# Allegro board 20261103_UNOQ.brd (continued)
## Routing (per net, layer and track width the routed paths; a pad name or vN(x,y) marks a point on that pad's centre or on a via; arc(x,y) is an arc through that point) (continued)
FORCED_USB_BOOT_N_R: length 12.3
  G7 w0.064: v1(14.73,23.6) 14.73,26.92 11.45,30.2 7.48,30.2 7.32,30.36 v1(7.31,30.36)
  BOTTOM w0.066: MCU1.A5 v1(14.73,23.6)
FORCED_USB_BOOT_POL_SEL: length 22.1
  TOP w0.066: v3(20.61,30.93) 20.77,30.77 20.77,28.91 21.18,28.5 21.18,27.4 21.45,27.13 21.45,18.4 22.21,17.64 R1314.1 R1313.2
  S3 w0.064: v3(26.57,29.68) 26.38,29.87 26.01,29.87 25.81,29.67 22.26,29.67 21.51,30.42 21.12,30.42 v3(20.61,30.93)
HPH_L: length 22.8
  TOP w0.15: PMIC1.L27 42.63,15.98 v3(42.67,16.02)
  S3 w0.15: v3(42.67,16.02) 42.65,15.99 v4(42.39,15.99)
  S6 w0.15: v4(42.39,15.99) 42.39,16.29 v1(42.4,16.3)
  BOTTOM w0.15: R2634.2 23.27,15.61 23.61,15.95 32.57,15.95 33.26,16.64 35.52,16.64 36.2,15.96 38.51,15.96 39.15,16.6 42.1,16.6 v1(42.4,16.3)
HPH_L_CONN: length 2.4
  BOTTOM w0.15: R2634.1 23.24,14.25 D26089.2 23.24,13.26 23.49,13 23.49,11.98
HPH_R: length 23.4
  TOP w0.15: v3(42.67,17.07) 42.39,17.07 41.87,16.55 PMIC1.J27
  S3 w0.15: v3(42.67,17.07) 42.67,17.07 v4(42.37,17.07)
  S6 w0.15: v4(42.37,17.07) v1(42.05,17.07)
  BOTTOM w0.15: v1(42.05,17.07) 41.86,16.88 39.02,16.88 38.33,16.19 36.39,16.19 35.6,16.98 33.14,16.98 32.47,16.31 23.38,16.31 22.73,15.66 R2635.2
HPH_R_CONN: length 2.5
  BOTTOM w0.15: 22.22,11.98 22.22,12.75 22.73,13.26 D26090.2 22.73,14.27 R2635.1
HPH_REF: length 27.4
  TOP w0.15: 42.12,16.26 PMIC1.K26
  TOP w0.2: 42.12,16.26 42.4,16.54 v3(42.67,16.54)
  S3 w0.2: v3(42.67,16.54) 42.92,16.54 42.93,16.54 v4(42.95,16.54)
  S6 w0.2: v1(42.65,16.54) v4(42.95,16.54)
  BOTTOM w0.2: v1(42.65,16.54) 42.65,17.15 ; R2633.2 22,14.59 22,15.98 22.99,16.97 29.66,16.97 30.71,18.02 35.19,18.02 36.67,16.54 38.19,16.54 39.3,17.65 41.8,17.65
  BOTTOM w0.203: 42.65,17.15 42.15,17.65 41.8,17.65
HPH_REF_CONN: length 2.1
  BOTTOM w0.203: R2633.1 21.68,13.39 20.95,12.66 20.95,11.98
HS_DET: length 51.5
  TOP w0.1: v3(43.81,20.02) 43.9,19.93 46.98,19.93 48.11,18.8 48.11,7.66 47.78,7.33 23.05,7.33 22.42,7.96 v3(22.42,8.72)
  S3 w0.064: v3(22.42,8.72) v4(22.42,9.16)
  S3 w0.1: v3(40.36,18.19) 40.39,18.21 40.39,18.29 41.2,19.1 42.09,19.1 42.75,19.76 43.56,19.76 v3(43.81,20.02)
  S6 w0.1: v4(22.42,9.16) 19.76,11.82 v1(19.68,11.82)
  BOTTOM w0.1: 19.68,11.98 v1(19.68,11.82)
JTAG_PS_HOLD: length 22
  TOP w0.066: v3(22.79,8.38) 35.02,8.38 R709.2
  S3 w0.064: v4(20.4,2.8) 20.12,3.08 20.12,5.5 22.79,8.17 v3(22.79,8.38)
  S6 w0.064: v1(21.71,2.8) v4(20.4,2.8)
  BOTTOM w0.066: v1(21.71,2.8) 22.37,2.14 22.64,2.14 TP1213.1
LDO1_EN: length 2
  BOTTOM w0.066: SB2801.2 11.68,39.33 R2801.2 11.7,40.05 U2801.1
LDO1_FB: length 3
  BOTTOM w0.203: U2801.6 13.6,41.08 12.83,40.31 R2803.1 12.83,40.01 R2802.2 13.34,40.01 C2803.2
LDO1_PG: length 8.2
  BOTTOM w0.203: Q2802.1 17.58,44.86 17.58,41.51 17.44,41.37 R2810.1 17.08,41.26 C2808.1 15.94,41.26 15.11,42.09 15.11,42.32 14.43,42.32 U2801.5
LDO2_EN: length 1
  BOTTOM w0.066: R2804.2 10.5,32.46 10.52,32.48 U2802.1
LDO2_FB: length 2.8
  BOTTOM w0.066: R2805.2 12.22,31.43 C2807.2 12.23,31.45 R2806.1 12.23,32.7 12.69,33.15 U2802.6
LED_MATRIX_0: length 22.5
  S3 w0.1: v3(19.03,7.74) 19.01,7.72 16.42,7.72 15.04,9.1 v4(13.22,9.1)
  S6 w0.1: v5(12.09,21.39) 12.04,21.34 12.04,18.67 9.32,15.95 9.32,13.49 13.18,9.63 13.18,9.14 v4(13.22,9.1)
  G7 w0.1: v5(12.09,21.39) 12.17,21.39 v1(12.9,22.11)
LED_MATRIX_0_R: length 84
  TOP w0.1: v2(10.04,21.05) 9.88,21.05 D27074.2 8.63,20.36 v2(8.36,20.36) ; D27091.1 v2(8,10.77) ; 15.39,26.86 v2(14.91,26.39) ; 15.39,26.86 15.88,27.35 v2(16.04,27.35) ; 15.39,26.86 15.39,27.03 13.42,29 ; 13.42,29 13.88,29.45 D27043.1 ; 13.42,29 D27044.2 12.91,28.22 D27057.1 11.07,26.39 v2(10.91,26.39) ; 19.48,35.36 D27002.2 ; 19.48,35.36 19.88,35.75 v2(20.04,35.75) ; 19.48,35.36 17.95,36.89 D27014.2 16.02,37.77 5.79,37.77 D27092.2 ; R2711.2 19.03,9.54 v2(20.04,10.55) ; D27003.1 19.07,30.59 D27004.2 18.91,30.26 v2(18.53,29.88) ; D27007.1 19.88,23.15 D27008.2 18.91,21.92 D27021.1 17.07,20.09 D27022.2
  G2 w0.1: v2(14.91,26.39) 14.68,26.39 13.58,25.29 13.58,23.02 v2(16.51,20.09) ; v2(10.91,26.39) 10.45,26.39 9.47,25.41 9.47,21.62 v2(10.04,21.05) ; v2(20.42,31.56) 20.42,35.37 v2(20.04,35.75) ; v2(18.53,29.88) 16.04,27.39 v2(16.04,27.35) ; v2(8.36,20.36) 6.31,18.31 6.31,12.4 D27091.1 v2(8,10.77) 8.23,11 11.92,11 12.67,10.25 16.48,10.25 16.78,10.55 v2(20.04,10.55)
LED_MATRIX_1: length 25.9
  S3 w0.1: v4(13.77,8.51) 15.02,8.51 16.17,7.36 21.25,7.36 v3(21.85,7.96)
  S6 w0.1: v4(13.77,8.51) 13.77,9.35 9.55,13.56 9.55,15.72 12.29,18.47 12.29,20.8 12.42,20.93 12.42,22.59 v1(12.4,22.61)
LED_MATRIX_1_R: length 74.8
  TOP w0.1: D27034.2 15.07,22.19 15.51,22.63 ; v2(20.04,33.65) D27015.1 17.88,33.65 v2(16.91,32.69) ; 15.51,22.63 15.51,22.76 13.53,24.74 ; 15.51,22.63 v2(16.04,23.15) ; v2(10.91,22.19) 11.07,22.19 D27059.1 12.04,23.42 D27046.2 13.07,24.29 13.53,24.74 ; v2(18.37,25.85) D27006.2 19.07,26.39 D27005.1 ; 13.53,24.74 D27045.1 14.23,25.06 v2(14.8,25.06) ; v2(20.59,17.83) 20.59,18.4 D27009.1 19.07,17.99 D27010.2 18.04,17.12 D27023.1 17.07,15.89 v2(16.91,15.89) ; D27076.2 9.07,15.89 v2(10.04,16.85) ; D27094.2 5.88,33.65 D27093.1 6.04,33.65 v2(6.33,33.65)
  G2 w0.1: v2(16.04,23.15) 16.04,20.91 16.8,20.15 16.8,18.86 16.44,18.5 16.44,16.35 v2(16.91,15.89) ; v2(20.59,17.83) 21.16,17.83 21.85,17.14 v2(21.85,8.92) ; v2(6.33,33.65) 7.09,33.65 8.79,35.35 10.44,35.35 12.75,33.04 15.39,33.04 15.74,32.69 v2(16.91,32.69) ; v2(20.4,27.37) 20.04,27.73 v2(20.04,33.65) 20.04,34.51 18.91,35.64 v2(18.91,36.89) ; v2(10.04,16.85) 10.39,17.2 10.39,20.55 10.91,21.07 v2(10.91,22.19) ; v2(14.8,25.06) 15.08,25.34 17.19,25.34 17.7,25.85 v2(18.37,25.85)
LED_MATRIX_2: length 26.1
  S3 w0.1: v4(12.52,9.02) 12.73,9.02 12.94,8.81 15.03,8.81 16.3,7.54 20.44,7.54 v3(20.89,7.99)
  S6 w0.1: v4(12.52,9.02) 12.52,9.96 9.07,13.41 9.07,16.08 11.79,18.8 11.79,20.31 11.81,20.33 11.81,21.51 12.19,21.89 12.19,22.76 12.4,22.97 v1(12.4,23.11)
LED_MATRIX_2_R: length 84
  TOP w0.1: 15.47,18.55 15.88,18.95 D27035.1 ; 15.47,18.55 D27036.2 ; 15.47,18.55 15.44,18.55 13.41,20.58 ; 13.41,20.58 D27048.2 12.91,19.82 D27061.1 11.88,18.95 v2(10.91,17.99) ; 13.41,20.58 13.88,21.05 D27047.1 ; D27011.1 19.07,13.79 D27012.2 18.04,12.92 D27025.1 17.07,11.69 v2(16.91,11.69) ; D27011.1 21.14,15.85 21.14,24.15 D27006.1 20.83,26.04 20.83,28.17 20.04,28.96 D27004.1 19.88,29.45 D27005.2 18.04,29.35 D27017.1 ; D27011.1 21.15,13.64 21.15,9.21 R2702.2 ; D27018.2 17.07,28.49 D27017.1 ; v2(10.04,12.23) D27077.1 ; v2(6.45,29.04) D27095.1 5.07,28.49 D27096.2 ; D27017.1 18.04,30.61 18.91,31.48 D27003.2
  G2 w0.1: v2(10.04,12.23) 10.04,11.55 10.31,11.28 ; v2(6.45,29.04) 7.34,28.15 7.34,22.71 8.91,21.14 8.91,20.39 7.6,19.07 7.6,14.67 9.21,13.06 10.33,13.06 10.91,12.48 ; v2(8.91,11.69) 9.31,11.28 10.31,11.28 ; 10.31,11.28 12.11,11.28 ; 12.11,11.28 12.78,10.61 15.31,10.61 16.39,11.69 v2(16.91,11.69) ; 12.11,11.28 10.91,12.48 ; 10.91,12.48 v2(10.91,17.99)
LED_MATRIX_3: length 28.1
  S3 w0.1: v3(19.95,7.99) 18.46,7.99 18.09,8.36 16.69,8.36 15.19,9.86 12.89,9.86 11.45,11.3 8.46,11.3 v4(8.32,11.16)
  S6 w0.1: v5(11.35,23.47) 11.35,23.4 11.21,23.26 11.21,22.94 9.86,21.59 9.86,19.05 7.85,17.04 7.85,12.7 8.05,12.5 8.05,11.43 v4(8.32,11.16)
  G7 w0.1: v1(12.06,23.45) 12.04,23.45 12.04,23.47 11.9,23.61 11.49,23.61 v5(11.35,23.47)
  BOTTOM w0.1: v1(12.06,23.45) 12.04,23.45 12.04,23.47 MCU1.G5
LED_MATRIX_3_R: length 75.7
  TOP w0.1: 13.42,16.39 14.91,14.9 D27038.2 15.88,14.75 v2(16.04,14.75) ; 13.42,16.39 13.88,16.85 D27049.1 ; 13.42,16.39 D27050.2 12.04,15.02 D27063.1 11.07,13.79 D27064.2 ; D27008.1 20.8,21.81 20.8,23.62 20.13,24.29 D27007.2 18.04,25.15 D27019.1 ; D27008.1 20.84,20.25 20.84,17.65 D27010.1 19.07,15.89 v2(18.91,15.89) ; D27008.1 19.88,21.05 D27009.2 ; v2(6.04,25.25) 5.07,24.29 D27098.2 ; v2(20.04,12.65) 20.82,11.87 20.82,9.9 19.95,9.03 R2703.2 ; v2(8.04,35.75) 7.88,35.75 D27080.2 ; D27019.1 17.88,25.25 D27020.2 ; D27019.1 v2(18.84,25.25) ; v2(14.91,34.79) 15.88,35.75 D27027.1
  G2 w0.1: v2(18.91,15.89) 20.04,14.75 v2(20.04,12.65) 19.03,12.65 16.93,14.75 v2(16.04,14.75) ; v2(6.04,25.25) 6.04,29.25 6.92,30.13 6.92,31.31 5.86,32.37 5.86,34.12 7.49,35.75 v2(8.04,35.75) 10.93,35.75 11.89,34.79 v2(14.91,34.79) 15.26,34.43 16.98,34.43 17.71,33.7 17.71,31.29 19.17,29.83 19.17,25.58 v2(18.84,25.25)
LED_MATRIX_4: length 24.1
  S3 w0.1: v4(10.08,10.99) 10.13,11.04 11.43,11.04 12.83,9.64 15.1,9.64 16.61,8.13 v3(17.21,8.13)
  S6 w0.1: v1(11.9,24.11) 11.9,23.4 11.56,23.07 11.56,22.8 10.29,21.53 10.29,18.82 8.23,16.76 8.23,12.98 8.84,12.37 8.84,11.66 9.32,11.18 9.89,11.18 v4(10.08,10.99)
LED_MATRIX_4_R: length 81.2
  TOP w0.1: v2(6.04,21.05) 5.07,20.09 D27100.2 ; D27030.2 15.88,31.55 D27029.1 16.04,31.45 D27017.2 ; D27015.2 17.88,35.75 v2(18.04,35.75) ; D27081.1 7.88,31.55 D27082.2 ; D27065.1 12.04,10.82 D27052.2 13.07,11.69 13.54,12.15 ; 13.54,12.15 D27051.1 ; 13.54,12.15 15.14,10.55 v2(16.04,10.55) 17.21,9.38 R2704.2 ; D27017.2 17.88,31.55 v2(18.04,31.55) ; D27017.2 16.91,29.38 16.03,28.5 16.03,28.36 17.04,27.35 17.88,27.35 ; 17.88,27.35 D27019.2 16.8,26.28 16.8,25.41 v2(17.15,25.06) ; 17.88,27.35 D27018.1
  G2 w0.1: v2(6.04,21.05) 5.76,21.33 5.76,29.77 v2(6.57,30.58) 6.57,30.92 5.51,31.98 5.51,35.14 7.65,37.28 v2(8.9,37.28) 8.92,37.26 v2(12.92,37.26) 15.58,37.26 17.09,35.75 v2(18.04,35.75) 18.51,35.28 18.51,32.02 v2(18.04,31.55) ; v2(16.04,10.55) 16.77,11.28 18.5,11.28 v2(18.91,11.69) 19.76,11.69 20.56,12.49 20.56,15.04 19.32,16.28 18.65,16.28 18.39,16.02 17.19,16.02 16.62,16.59 16.62,18.29 17.03,18.7 17.03,20.32 16.66,20.69 16.66,21.5 18.04,22.88 v2(18.04,23.15) 18.04,24.17 v2(17.15,25.06)
LED_MATRIX_5: length 28.1
  S3 w0.1: v3(18.08,7.99) 17.99,7.9 16.51,7.9 15,9.41 12.76,9.41 11.86,10.31 10.4,10.31 10.01,9.92 v4(10.01,9.73)
  S6 w0.1: v5(10.95,23.5) 10.87,23.42 10.82,23.42 10.67,23.27 10.67,23.22 10.67,23.22 10.67,22.96 9.47,21.77 9.47,19.23 7.47,17.22 7.47,12.88 7.24,12.65 7.24,11.22 7.66,10.8 9.45,10.8 10.01,10.24 v4(10.01,9.73)
  G7 w0.1: v5(10.95,23.5) 11.18,23.27 11.74,23.27 v1(11.9,23.11)
LED_MATRIX_5_R: length 65.9
  TOP w0.1: R2705.2 18.08,10.51 D27026.1 17.99,10.6 v2(17.99,11.7) ; D27042.2 13.07,32.69 D27041.1 14.04,33.55 v2(14.91,32.69) 15.07,32.69 D27028.1 16.04,34.69 v2(15.78,34.95) ; v2(16.91,13.79) 17.07,13.79 17.5,14.21 ; v2(8.04,27.35) 7.88,27.35 v2(6.91,26.39) ; v2(6.04,16.85) 5.88,16.85 D27102.2 ; v2(17.02,22.91) 16.91,22.81 D27021.2 16.91,20.99 16.11,20.19 16.11,19.89 17.5,18.5 17.5,18.42 ; 17.5,18.42 D27022.1 ; 17.5,18.42 17.07,17.99 D27023.2 16.91,16.81 16.15,16.05 16.15,15.56 17.5,14.21 ; 17.5,14.21 D27024.1 ; v2(8.91,32.69) 9.88,33.65 D27067.1 10.91,34.52 D27054.2 11.88,35.75 v2(12.04,35.75)
  G2 w0.1: v2(12.04,35.75) 12.92,35.75 14.06,36.89 v2(14.91,36.89) 14.91,35.82 v2(15.78,34.95) ; v2(17.99,11.7) 17.93,11.7 16.91,12.72 v2(16.91,13.79) ; v2(14.91,32.69) 14.91,31.65 16.04,30.52 v2(16.04,29.45) 15.48,28.89 15.48,26.37 14.29,25.18 14.29,24.51 15.01,23.79 16.14,23.79 v2(17.02,22.91) ; v2(8.04,27.35) 8.3,27.61 8.3,30.89 8.91,31.5 v2(8.91,32.69) ; v2(6.04,16.85) 6.04,18.58 6.54,19.08 6.54,26.02 v2(6.91,26.39)
LED_MATRIX_6: length 22
  S3 w0.1: v3(7.87,7.76) 8.14,7.49 9.81,7.49 10.59,8.27 v4(10.59,9.92)
  S6 w0.1: v4(10.59,9.92) 10.59,10.01 9.63,10.97 8.99,10.97 8.51,11.46 8.51,12.4 8.03,12.88 8.03,16.89 10.06,18.92 10.06,21.55 11.38,22.87 11.38,23.14 11.63,23.39 11.63,23.88 v1(11.4,24.11)
LED_MATRIX_6_R: length 67.8
  TOP w0.1: 15.54,24.75 D27032.1 ; 15.54,24.75 15.54,24.83 v2(14.04,26.33) ; 15.54,24.75 15.07,24.29 D27033.2 ; 15.54,24.75 16.8,23.49 16.8,23.02 16.04,22.26 D27034.1 15.88,21.05 v2(14.91,20.09) ; v2(14.91,28.49) 14.91,29.56 14.04,30.43 D27042.1 D27055.1 ; v2(17.12,10.09) 17.12,10.49 15.92,11.69 D27039.2 15.88,12.65 v2(16.04,12.65) ; v2(6.04,12.65) 5.88,12.65 D27104.2 4.91,10.55 5.89,9.57 7.02,9.57 R2706.2 ; D27055.1 12.04,32.75 12.84,33.55 12.84,34.72 D27041.2 13.88,35.75 D27040.1 ; D27055.1 11.07,30.59 D27056.2 10.04,29.72 D27069.1 9.07,28.49 v2(8.91,28.49) ; v2(14.91,15.89) 15.07,15.89 D27036.1 ; v2(8.04,23.15) 7.88,23.15 D27086.2
  G2 w0.1: v2(8.91,28.49) 8.91,26.84 8.04,25.97 v2(8.04,23.15) ; v2(6.04,12.65) 6.04,12.15 7.77,10.42 8.04,10.42 8.38,10.76 11.55,10.76 12.22,10.09 v2(17.12,10.09) ; v2(16.04,12.65) 14.91,13.79 v2(14.91,15.89) v2(14.91,20.09) ; v2(14.91,28.49) 14.91,27.2 v2(14.04,26.33)
LED_MATRIX_7: length 18.1
  S3 w0.1: v3(11.34,7.76) 11.97,8.39 11.97,9.86 11.79,10.04 11.27,10.04 v4(11.18,9.95)
  S6 w0.1: v5(11.56,22.11) 11.44,22.11 10.74,21.41 10.74,18.57 8.66,16.48 8.66,13.23 11.18,10.71 v4(11.18,9.95)
  G7 w0.1: v1(11.9,22.11) v5(11.56,22.11)
LED_MATRIX_7_R: length 53.4
  TOP w0.1: D27050.1 13.07,13.79 v2(12.91,13.79) ; v2(12.91,17.99) 13.07,17.99 D27048.1 ; v2(8.91,24.29) 9.88,25.25 v2(10.04,25.25) ; D27043.2 12.04,29.72 v2(12.04,29.45) ; R2707.2 13.17,10.55 D27052.1 ; v2(10.91,32.69) 11.07,32.69 D27054.1 ; v2(10.02,34.88) 10.91,35.77 D27053.2 ; D27046.1 13.88,23.15 v2(12.91,22.19) ; v2(14.04,27.35) 13.88,27.35 D27045.2 ; D27088.2 7.88,18.95 v2(8.04,18.95)
  G2 w0.1: v2(8.04,18.95) 9.26,20.17 9.26,21.39 8.91,21.74 v2(8.91,24.29) ; v2(14.04,27.35) 13.13,27.35 12.93,27.55 ; 10.9,25.25 12.91,23.25 v2(12.91,22.19) v2(12.91,17.99) v2(12.91,13.79) 12.91,12.47 14.04,11.34 v2(14.04,10.94) ; 10.9,25.25 12.93,27.28 12.93,27.55 ; 10.9,25.25 v2(10.04,25.25) ; 12.93,27.55 12.04,28.44 v2(12.04,29.45) 12.04,30.6 10.91,31.73 v2(10.91,32.69) 10.02,33.58 v2(10.02,34.88)
LED_MATRIX_8: length 17.3
  S3 w0.1: v4(11.55,9.6) 11.55,8.85 v3(10.48,7.78)
  S6 w0.1: v5(11.51,21.13) 11.38,21.13 11.05,20.8 11.05,18.44 8.86,16.26 8.86,13.34 11.55,10.65 v4(11.55,9.6)
  G7 w0.1: v1(12.27,21.13) v5(11.51,21.13)
  BOTTOM w0.1: MCU1.F1 v1(12.27,21.13)
LED_MATRIX_8_R: length 47.1
  TOP w0.1: 11.49,24.7 11.49,24.83 9.43,26.89 9.43,26.91 ; 11.49,24.7 11.07,24.29 D27059.2 10.04,23.42 D27072.1 10.04,22.01 11.52,20.53 ; 11.49,24.7 D27058.1 ; 11.51,12.13 D27064.1 ; 11.51,12.13 10.1,13.54 10.1,13.87 10.91,14.68 D27063.2 11.88,16.85 v2(12.04,16.85) ; 11.51,12.13 11.07,11.69 v2(10.91,11.69) 10.91,9.17 R2708.2 ; D27057.2 10.91,28.22 D27070.1 9.88,27.35 9.43,26.91 ; D27089.1 7.88,14.75 v2(6.91,13.79) ; 9.43,31.11 D27069.2 8.91,29.33 8.14,28.56 8.14,28.2 9.43,26.91 ; 9.43,31.11 8.03,32.51 8.03,32.68 8.91,33.56 D27067.2 9.07,34.79 D27066.1 ; 9.43,31.11 9.88,31.55 D27068.1 ; v2(10.91,20.09) 11.07,20.09 11.52,20.53 ; 9.43,26.91 D27071.2 ; 11.52,20.53 D27060.1
  G2 w0.1: v2(10.91,11.69) 10.05,12.55 8.15,12.55 v2(6.91,13.79) ; v2(10.91,20.09) 10.91,19.06 12.04,17.93 v2(12.04,16.85)
LED_MATRIX_9: length 17.9
  S3 w0.1: v4(10.5,10.65) 10.15,10.65 9.65,10.15 9.65,7.88 v3(9.55,7.78)
  S6 w0.1: v1(11.76,22.53) 11.61,22.53 10.52,21.44 10.52,18.73 8.43,16.65 8.43,13.13 9.63,11.94 9.7,11.94 10.5,11.14 v4(10.5,10.65)
  BOTTOM w0.1: v1(11.76,22.53) 11.82,22.53 MCU1.G3
LED_MATRIX_9_R: length 44
  TOP w0.1: 7.46,24.84 7.42,24.84 6.08,26.18 6.08,26.46 6.91,27.29 D27083.2 7.07,28.49 7.54,28.95 ; 7.46,24.84 D27085.2 ; 7.46,24.84 7.88,25.25 D27084.1 8.04,24.02 8.91,23.15 D27073.2 8.04,21.32 D27086.1 7.88,21.05 7.42,20.59 ; D27079.2 6.91,35.67 6.16,34.92 6.16,34.48 7.51,33.13 ; v2(6.91,15.89) 7.07,15.89 D27088.1 8.91,17.72 D27075.2 9.46,18.53 ; 9.46,18.53 9.46,18.55 7.42,20.59 ; 9.46,18.53 9.88,18.95 D27074.1 ; 7.42,20.59 D27087.2 ; 7.51,33.13 D27080.1 ; 7.51,33.13 7.07,32.69 D27081.2 6.91,31.56 6.08,30.73 6.08,30.36 7.49,28.95 7.54,28.95 ; 7.54,28.95 D27082.1 ; D27090.1 8.51,13.12 ; 8.51,13.12 v2(8.51,13.23) 8.91,13.64 D27077.2 9.88,14.75 D27076.1 ; 8.51,13.12 8.51,13.04 10.04,11.51 D27078.1 10.04,9.23 R2709.2
  G2 w0.1: v2(8.51,13.23) 6.91,14.83 v2(6.91,15.89)
LED_MATRIX_10: length 18.1
  S3 w0.1: v3(8.69,7.77) 8.69,9.05 7.79,9.95 v4(7.79,11.14)
  S6 w0.1: v4(7.79,11.14) 7.65,11.28 7.65,17.12 9.65,19.13 9.65,21.67 10.92,22.94 v5(10.92,23.16)
  G7 w0.1: v5(10.92,23.16) 10.97,23.11 11.34,23.11 v1(11.5,22.95)
  BOTTOM w0.1: MCU1.H4 11.4,23.05 v1(11.5,22.95)
LED_MATRIX_10_R: length 38.1
  TOP w0.1: D27100.1 5.07,17.99 v2(4.91,17.99) ; 5.54,14.25 D27102.1 ; 5.54,14.25 5.07,13.79 v2(4.91,13.79) ; 5.54,14.25 5.54,14.16 6.8,12.9 D27091.2 6.04,11.14 D27104.1 6.87,10.55 R2710.2 ; v2(4.91,26.39) 5.07,26.39 D27096.1 ; v2(4.91,34.79) 5.07,34.79 D27092.1 ; v2(4.91,22.19) 5.07,22.19 D27098.1 ; D27094.1 5.88,31.55 v2(4.91,30.59)
  G2 w0.1: v2(4.91,13.79) v2(4.91,17.99) v2(4.91,22.19) v2(4.91,26.39) v2(4.91,30.59) v2(4.91,34.79)
LED_MATRIX_11: length 2.4
  BOTTOM w0.051: MCU1.M5 9.16,23.85 8.61,23.85
  BOTTOM w0.1: 8.61,23.85 7.84,23.08 TP2506.1
LED_PWR: length 2.2
  TOP w0.254: R2735.2 29.81,65.61 D27201.1
LINEOUT_M: length 2.3
  BOTTOM w0.254: C514.1 26.76,15.31 25.19,15.31 25.02,15.14 R2632.2
LINEOUT_M_C: length 26.9
  S3 w0.15: v4(45.23,19.02) 45,19.25 42.95,19.25 41.89,18.2 41.25,18.2 41,17.95 40.68,17.95 v3(40.67,17.96)
  S6 w0.15: v1(45.53,19.04) 45.49,19.08 45.29,19.08 v4(45.23,19.02)
  BOTTOM w0.254: C514.2 27.51,15.21 33.64,15.21 33.91,14.94 38.19,14.94 39.1,15.85 43.85,15.85 44.6,16.6 45.08,16.6 45.9,17.42 45.9,18.67 v1(45.53,19.04)
LINEOUT_M_CONN: length 2.5
  BOTTOM w0.254: 24.76,11.98 24.76,13.01 25.02,13.26 D26088.2 25.02,14.37 R2632.1
LINEOUT_P: length 1.2
  BOTTOM w0.254: R2631.2 26.46,14.88 26.73,14.61 C513.1
LINEOUT_P_C: length 28
  S3 w0.15: v4(45.56,19.45) 45.5,19.51 42.77,19.51 41.74,18.48 41.17,18.48 40.95,18.26 v3(40.95,18.24)
  S6 w0.15: v1(45.85,19.47) 45.81,19.51 45.62,19.51 v4(45.56,19.45)
  BOTTOM w0.254: C513.2 27.71,14.61 27.98,14.88 33.48,14.88 33.77,14.6 38.33,14.6 39.23,15.5 43.98,15.5 44.74,16.26 45.21,16.26 46.24,17.29 46.24,18.83 45.85,19.22 v1(45.85,19.47)
LINEOUT_P_CONN: length 2.5
  BOTTOM w0.254: R2631.1 25.84,14.37 D26087.2 25.84,13.31 26.03,13.12 26.03,11.98
LNBBCLK1: length 6.8
  S3 w0.064: v3(30.3,13.56) 30.49,13.56 30.6,13.45 30.72,13.45 31.5,12.67 32.72,12.67 32.72,12.66 33.53,12.66 33.86,12.99 33.86,13.94 34.77,14.86 35.26,14.86 v3(35.28,14.88)
LNBBCLK2: length 6.1
  S3 w0.064: v3(30.28,12.52) 30.76,12.52 31.08,12.2 33.82,12.2 34.35,12.73 34.48,12.86 34.48,13.7 34.65,13.87 v3(34.65,14.28)
LNBBCLK2_R: length 0.5
  TOP w0.066: R703.1 C720.1
MCU_BOOT0: length 39.8
  S3 w0.064: v4(13.55,35.58) 13.8,35.82 14.55,35.82 14.86,35.51 v4(18.96,35.51)
  S6 w0.064: v1(19.07,36.29) 18.79,36.01 18.79,35.68 v4(18.96,35.51) ; v5(12.89,25.13) 12.89,25.87 11.96,26.8 11.96,32.8 13.55,34.39 v4(13.55,35.58) 13.55,35.87 v1(13.54,35.88) ; v1(6.49,41.7) 6.58,41.79 6.58,42.35 v1(6.31,42.62)
  G7 w0.064: v5(12.89,25.13) 13.67,24.36 13.67,23.85 v1(13.9,23.61)
  BOTTOM w0.066: JANALOG1.1 3.6,41.7 v1(6.49,41.7) 7.72,41.7 10.21,39.2 10.7,39.2 11.53,38.37 12.87,38.37 13.54,37.7 v1(13.54,35.88) ; U1101.10 18.21,37.72 19.24,36.69 19.24,36.43 19.1,36.29 v1(19.07,36.29) ; R2621.1 6.31,43.26 v1(6.31,42.62)
MCU_BOOT0_1P8V: length 12.7
  TOP w0.066: v3(23.72,40.23) 23.83,40.34 24.31,40.34 SOC1.AH1
  S3 w0.064: v3(23.72,40.23) 23.47,39.98 21.11,39.98 20.43,40.66 v4(20.23,40.66)
  S6 w0.064: v1(20,40.44) v4(20.23,40.66)
  BOTTOM w0.066: v1(20,40.44) 19.96,40.39 18.82,40.39 18.65,40.22 15.93,40.22 15.22,39.5 15.22,38.23 15.74,37.71 16.04,37.71 U1101.2
MCU_BT_UART_CTS_R: length 1.8
  TOP w0.064: R2906.2 4.74,61 U2901.14
MCU_BT_UART_RTS_R: length 5.2
  TOP w0.064: R2904.2 4.8,63.17 8.79,63.17 U2901.11
MCU_BT_UART_RX_R: length 7
  TOP w0.064: R2901.2 23.16,62.23 20.82,62.23 20.28,61.69 17.97,61.69 U2901.4
MCU_BT_UART_TX_R: length 2
  TOP w0.064: U2901.41 21.43,60.05 R2908.2
MCU_CRS_SYNC_PA10: length 59.2
  S6 w0.064: v5(4.67,26.49) 4.67,25.32 3.76,24.41 3.76,15.32 4.58,14.5 4.58,6.71 6.04,5.25 9.01,5.25 11.11,3.15 v1(15.1,3.15)
  G7 w0.064: v1(12.4,26.61) 12.16,26.85 8.05,26.85 7.87,27.03 7.39,27.03 6.91,27.51 5.69,27.51 v5(4.67,26.49)
  BOTTOM w0.066: v1(15.1,3.15) 15.84,3.89 23.23,3.89 23.38,4.04 23.38,5.04 24.73,6.39 29.6,6.39 29.84,6.63 JMISC1.25
MCU_I2C2_SCL: length 75.7
  S6 w0.064: v1(8.34,53.48) 8.14,53.28 8.14,46.7 9.07,45.77 9.07,29.91 10.64,28.34 v1(10.64,27.89)
  BOTTOM w0.051: 10.64,25.86 v1(10.64,27.89)
  BOTTOM w0.066: MCU1.K9 10.64,25.86 ; v1(8.34,53.48) 8.59,53.23 11.04,53.23 12.65,51.62 14.51,51.62 18.96,47.17 18.96,43.38 20.38,41.96 33.98,41.96 34.82,42.8 39.75,42.8 43.36,46.41 R2643.2 R2644.1
MCU_I2C2_SCL_CONN: length 10
  BOTTOM w0.066: R2644.2 47.32,46.41 47.68,46.05 51.71,46.05 52.2,46.53 52.2,48.82 51.24,49.78 JDIGITAL1.18
MCU_I2C2_SDA: length 76.4
  S6 w0.064: v1(10.26,27.94) 10.26,28.42 8.87,29.81 8.87,45.75 7.98,46.64 7.98,53.51 v1(7.9,53.59)
  BOTTOM w0.051: 10.13,26.01 10.13,27.81
  BOTTOM w0.066: v1(7.9,53.59) 8,53.69 8.5,53.69 8.8,53.39 11.11,53.39 12.72,51.78 14.58,51.78 19.12,47.23 19.12,43.45 20.45,42.12 33.91,42.12 34.75,42.96 39.63,42.96 43.63,46.96 R2642.2 R2645.1 ; 10.13,27.81 v1(10.26,27.94) ; 10.13,26.01 9.9,25.77 MCU1.L9
MCU_I2C2_SDA_CONN: length 4.3
  BOTTOM w0.066: R2645.2 50.52,46.96 JDIGITAL1.17
MCU_I2C4_SCL_PD12: length 43.9
  TOP w0.066: v3(7.62,7.02) 7.83,7.23 12.95,7.23 13.16,7.44 15.67,7.44 16.01,7.1 R2614.2 16,7.07 R2615.1
  S3 w0.064: v3(7.62,7.02) 5.68,7.02 4.57,5.91 3.86,5.91 3.35,6.42 1.48,6.42 1.07,6.83 1.07,18.28 3.15,20.36 v4(3.15,21.44)
  S6 w0.064: v4(3.15,21.44) 3.39,21.44 v5(3.48,21.35)
  G7 w0.064: v5(3.48,21.35) 3.64,21.35 4.67,22.38 4.67,23.09 4.93,23.34 7.75,23.34 8,23.6 9.58,23.6 9.84,23.86 v1(10.15,23.86)
  BOTTOM w0.051: 10.15,25.74 10.15,25.43 10.21,25.37 10.57,25.37 10.67,25.27 10.67,23.95 10.58,23.86 v1(10.15,23.86)
  BOTTOM w0.066: 10.15,25.74 10.4,25.99 MCU1.K10
MCU_I2C4_SCL_PD12_CONN: length 1.6
  TOP w0.066: R2615.2 15.47,6.41 15.85,6.03 QWIIC1.4
MCU_I2C4_SCL_PF14: length 52.5
  S3 w0.064: v6(3.3,14.2) 5.01,14.2 7.36,11.85 12.32,11.85 13.43,10.74 23.1,10.74 24.62,9.22 v4(25.35,9.22)
  S6 w0.064: v4(25.35,9.22) 25.37,9.19 v5(25.37,8.89)
  G7 w0.064: v5(25.37,8.89) 25.53,9.04 26.61,9.04 31.37,13.81 35.55,13.81 v1(35.82,13.54)
  BOTTOM w0.058: 8.58,24.36 9.65,24.36 MCU1.L6 ; v6(3.3,14.2) 3.63,14.2 4.49,15.05 4.49,21.89 ; 6.54,23.02 7.16,23.64 7.86,23.64
  BOTTOM w0.066: 8.58,24.36 7.86,23.64 ; v1(35.82,13.54) R2668.1 ; 4.49,21.89 5.62,23.02 6.54,23.02
MCU_I2C4_SCL_PF14_CONN: length 1.8
  BOTTOM w0.066: 36.19,11.98 36.19,12.72 36.85,13.38 R2668.2
MCU_I2C4_SDA_PD13: length 48.5
  TOP w0.066: R2616.1 14.34,7.09 ; 14.34,7.09 14.21,7.22 13.21,7.22 13.05,7.06 10.56,7.06 v3(9.2,5.7) ; 14.34,7.09 R2613.2
  S3 w0.064: v4(2.97,26.67) 1.73,26.67 0.56,25.5 0.56,4.72 1.67,3.61 4.48,3.61 5.79,4.92 8.42,4.92 v3(9.2,5.7)
  S6 w0.064: v4(2.97,26.67) 3.07,26.67 v5(3.45,26.29)
  G7 w0.064: v5(3.45,26.29) 3.91,26.29 5.31,27.69 8.79,27.69 9.45,27.03 10.31,27.03 v1(10.4,27.11)
MCU_I2C4_SDA_PD13_CONN: length 1.5
  TOP w0.066: R2616.2 14.86,5.11 QWIIC1.3
MCU_I2C4_SDA_PF15: length 48.9
  S3 w0.064: v6(3.43,13.67) 5.29,13.67 7.29,11.67 12.25,11.67 13.35,10.57 23.08,10.57 24.86,8.79 v4(24.94,8.79)
  S6 w0.064: v5(25.37,8.53) 25.2,8.53 v4(24.94,8.79)
  G7 w0.064: v5(25.37,8.53) 26.41,8.53 31.42,13.54 v1(33.78,13.54)
  BOTTOM w0.058: 6.59,22.86 7.22,23.49 7.92,23.49 ; 4.63,21.83 4.63,14.87 v6(3.43,13.67)
  BOTTOM w0.066: MCU1.N6 8.54,24.11 7.92,23.49 ; 6.59,22.86 5.67,22.86 4.63,21.83 ; R2669.1 v1(33.78,13.54)
MCU_I2C4_SDA_PF15_CONN: length 1.6
  BOTTOM w0.066: R2669.2 34.8,12.1 34.92,11.98
MCU_JTAG_NJTRST_PB4: length 77.2
  TOP w0.066: JDIGITAL1.9 49.5,25.62 49.5,6.91 48.74,6.15 24.66,6.15 23.31,4.8 20.79,4.8 v3(20.7,4.71)
  S3 w0.064: v3(20.7,4.71) 21.71,5.72 21.71,6.75 23.19,8.23 v4(23.19,9.64)
  S6 w0.064: v4(23.19,9.64) 23.19,10.59 20.04,13.74 v1(20.04,16.36)
  BOTTOM w0.066: MCU1.B6 14.64,24.36 16.41,24.36 16.49,24.28 17.55,24.28 TP2504.1 18.9,24.13 20.04,22.99 v1(20.04,16.36)
MCU_JTAG_SWCLK: length 24.2
  S3 w0.064: v4(14.25,35.35) 14.69,35.35 14.99,35.05 19.13,35.05 v4(19.25,35.18)
  S6 w0.064: v4(14.25,35.35) 14.2,35.3 14.2,34.23 13.67,33.7 13.67,30.09 14.48,29.28 14.48,28.35 13.87,27.74 13.87,27.15 13.74,27.03 13.74,26.27 v1(13.9,26.11) ; v4(19.25,35.18) 19.41,35.33 19.41,36.69 19.16,36.94 v1(19.16,37.55)
  BOTTOM w0.051: 15.37,25.86 14.15,25.86 v1(13.9,26.11)
  BOTTOM w0.066: U1101.8 17.46,38.51 18.72,38.51 19.02,38.21 19.02,37.69 v1(19.16,37.55) ; 15.37,25.86 15.75,26.24 17.07,26.24 TP2503.1
MCU_JTAG_SWCLK_1P8V: length 13.3
  S3 w0.064: v3(26.57,39.28) 26.37,39.48 26.37,39.75 25.98,40.13 24.18,40.13 23.75,39.7 20.29,39.7 v4(20.14,39.85)
  S6 w0.064: v4(20.14,39.85) 20.04,39.95 v1(19.75,39.95)
  BOTTOM w0.066: U1101.4 16.04,38.51 15.76,38.51 15.54,38.73 15.54,39.3 16.09,39.85 18.95,39.85 19.05,39.95 v1(19.75,39.95)
MCU_JTAG_SWDIO: length 18.8
  S3 w0.064: v4(14.38,36.42) 14.59,36.63 17.11,36.63 17.75,35.99 19.05,35.99 v4(19.11,35.93)
  S6 w0.064: v4(14.38,36.42) 13.87,35.91 13.87,34.31 12.4,32.84 v1(12.4,27.11) ; v4(19.11,35.93) 19.11,36.01 19.28,36.18 19.28,36.63 19.03,36.88 19.03,37.25 v1(18.82,37.46)
  BOTTOM w0.066: U1101.9 17.96,38.12 18.06,38.02 TP2502.1 18.82,37.76 v1(18.82,37.46)
MCU_JTAG_SWDIO_1P8V: length 14
  S3 w0.064: v4(20.56,40.16) 20.88,39.84 23.68,39.84 24.13,40.28 26.06,40.28 26.57,39.78 v3(26.57,39.68)
  S6 w0.064: v4(20.56,40.16) 20.53,40.13 20.36,40.13 v1(20.24,40.25)
  BOTTOM w0.066: U1101.3 16.04,38.11 15.74,38.11 15.39,38.46 15.39,39.42 15.98,40.01 18.68,40.01 18.84,40.18 20.17,40.18 v1(20.24,40.25)
MCU_JTAG_SWO_PB3: length 77.1
  S3 w0.064: v4(16.43,1.75) 17.45,1.75 17.93,1.27 21.09,1.27 23.67,3.85 23.67,5.91 24.31,6.55 31.41,6.55 32.71,5.26 47.96,5.26 49.53,6.83 49.53,8.89 JDIGITAL1.3
  S6 w0.064: v4(16.43,1.75) 16.36,1.83 16.36,3.12 11.26,8.22 8.82,8.22 6.32,10.72 6.32,13.06 6.49,13.22 6.49,17.56 8.02,19.08 8.02,19.86 8.18,20.02 8.18,22.83 7.98,23.04 7.98,23.39 8.41,23.83 8.74,23.83 9.17,24.26 9.17,24.92 v5(8.99,25.1)
  G7 w0.064: v1(13.4,24.11) 12.62,24.89 11.67,24.89 11.46,25.1 v5(8.99,25.1)
MCU_JTAG_TDI: length 2.7
  BOTTOM w0.051: MCU1.A10 15.34,26.11
  BOTTOM w0.066: 15.34,26.11 15.7,26.47 17.2,26.47 TP2501.1
MCU_LED1_BLU: length 78.9
  G7 w0.064: v1(10.52,29.24) 10.44,29.16 9.61,29.16 9.56,29.21 8,29.21 7.77,29.44 3.63,29.44 3.45,29.26 2.13,29.26 1.28,28.41 1.28,4.4 1.78,3.89 4.28,3.89 5.62,5.23 8.85,5.23 12.61,1.47 21.14,1.47 23.02,3.35 23.02,5.76 24.14,6.88 34.38,6.88 34.82,6.44 v1(35.37,6.44)
  BOTTOM w0.058: MCU1.B13 14.4,27.97 13.51,28.85 12.12,28.85 11.68,29.29 10.57,29.29 v1(10.52,29.24)
MCU_LED1_BLU_D: length 12.3
  TOP w0.066: 46.4,3.98 46.4,4.07 45.65,4.82 40.69,4.82 40.33,4.46 37.64,4.46 v3(37.55,4.55)
  S3 w0.064: v4(37.25,4.55) v3(37.55,4.55)
  S6 w0.064: v1(36.51,4.85) 36.82,4.55 v4(37.25,4.55)
  BOTTOM w0.066: v1(36.51,4.85) 36.48,4.89 36.48,6.29 R2731.1
MCU_LED1_GRN: length 82.8
  G7 w0.064: v1(1.35,28.88) 1.14,28.67 1.14,4.34 1.73,3.76 4.34,3.76 5.68,5.09 8.8,5.09 12.56,1.33 21.2,1.33 23.16,3.29 23.16,5.7 24.2,6.74 34.25,6.74 35.07,5.93 37.03,5.93 37.31,6.21 v1(37.31,6.25) ; v1(3.58,28.52) 4.04,28.52 4.5,28.99 7.51,28.99 7.79,28.7 9.42,28.7 9.45,28.73 9.65,28.73 9.86,28.52 v1(11.46,28.52)
  BOTTOM w0.058: v1(11.46,28.52) 11.58,28.4 13,28.4 13.64,27.76 13.64,25.85 MCU1.D9
  BOTTOM w0.066: v1(3.58,28.52) 3.1,29.01 1.47,29.01 v1(1.35,28.88)
MCU_LED1_GRN_D: length 13
  TOP w0.066: 46.4,3.13 46.4,3.28 v3(46.92,3.8)
  S3 w0.064: v3(46.92,3.8) 46.83,3.89 44.22,3.89 44.02,3.69 43.21,3.69 42.8,4.1 41.03,4.1 40.79,3.86 38.16,3.86 v4(37.98,4.04)
  S6 w0.064: v1(38.27,3.9) 38.12,3.9 v4(37.98,4.04)
  BOTTOM w0.066: R2730.1 v1(38.27,3.9)
MCU_LED1_RED: length 83.6
  G7 w0.064: v1(11.1,28.78) 9.8,28.78 9.7,28.87 9.4,28.87 9.38,28.85 7.85,28.85 7.57,29.14 4.42,29.14 4.06,28.78 v1(3.81,28.78) ; v1(1.35,29.26) 1.35,29.24 1,28.89 1,4.28 1.67,3.62 4.42,3.62 5.74,4.94 8.73,4.94 12.49,1.18 21.26,1.18 23.31,3.23 23.31,5.64 24.26,6.59 34.19,6.59 35.06,5.72 38.59,5.72 v1(39.11,6.24)
  BOTTOM w0.058: v1(11.1,28.78) 11.66,28.78 11.88,28.56 13.27,28.56 13.9,27.94 MCU1.C13
  BOTTOM w0.066: v1(3.81,28.78) 3.73,28.85 3.48,28.85 3.17,29.16 1.44,29.16 1.35,29.25 v1(1.35,29.26)
MCU_LED1_RED_D: length 9
  TOP w0.066: v3(38.55,4.25) 38.55,4.28 38.59,4.32 40.39,4.32 40.75,4.68 45.23,4.68 45.55,4.36 D27401.2
  S3 w0.064: v3(38.55,4.25) 38.69,4.39 v4(38.69,4.54)
  S6 w0.064: v1(39.11,5.01) 38.69,4.59 v4(38.69,4.54)
  BOTTOM w0.066: R2729.1 v1(39.11,5.01)
MCU_LED2_BLU: length 90.4
  G7 w0.064: v1(9.73,29.57) 9.68,29.51 8.13,29.51 7.9,29.74 4.56,29.74 4.22,30.08 4.22,31.32 3.86,31.68 1.86,31.68 1.3,31.11 1.3,29.74 0.86,29.31 0.86,4.23 1.61,3.48 4.47,3.48 5.8,4.8 8.68,4.8 12.43,1.04 21.32,1.04 23.45,3.17 23.45,5.58 24.32,6.45 34.13,6.45 35.01,5.58 39.51,5.58 v1(39.66,5.73)
  BOTTOM w0.058: v1(9.73,29.57) 9.86,29.69 11.8,29.69 12.32,29.17 13.7,29.17 14.9,27.98 MCU1.A13
  BOTTOM w0.066: v1(39.66,5.73) 39.66,4.87 R2734.2
MCU_LED2_BLU_D: length 10.2
  TOP w0.066: v3(39.49,4.7) 39.91,5.12 47.06,5.12 48.2,3.98 D27402.3
  S3 w0.064: v4(39.84,4.37) 39.82,4.37 v3(39.49,4.7)
  S6 w0.064: v1(40.13,4.37) v4(39.84,4.37)
MCU_LED2_GRN: length 91.8
  G7 w0.064: v1(3.78,31.34) 3.78,30.13 4.33,29.58 7.83,29.58 8.06,29.35 9.62,29.35 9.63,29.33 10.08,29.33 v1(10.19,29.44) ; v1(1.88,31.88) 1.83,31.88 1.16,31.21 1.16,29.8 0.73,29.37 0.73,4.17 1.55,3.34 4.53,3.34 5.85,4.66 8.62,4.66 12.38,0.9 21.38,0.9 23.59,3.11 23.59,5.52 24.38,6.31 34.08,6.31 34.95,5.44 39.76,5.44 40.18,5.86 v1(40.18,6.32)
  BOTTOM w0.058: v1(10.19,29.44) 10.26,29.51 11.71,29.51 12.2,29.03 13.59,29.03 14.66,27.97 14.66,27.51 14.49,27.35 14.24,27.35 14.15,27.25 14.15,26.86 MCU1.C11
  BOTTOM w0.066: v1(3.78,31.34) 3.35,31.78 1.98,31.78 v1(1.88,31.88)
MCU_LED2_GRN_D: length 10.6
  TOP w0.066: D27402.4 48.3,3.28 v3(48.77,3.75)
  S3 w0.064: v4(40.56,4.27) 40.61,4.22 43.02,4.22 43.33,3.91 43.8,3.91 44,4.11 48.41,4.11 v3(48.77,3.75)
  S6 w0.064: v1(40.25,5.3) 40.25,4.58 v4(40.56,4.27)
MCU_LED2_RED: length 88
  G7 w0.064: v1(10.82,29.03) 10.74,28.96 10.46,28.96 10.41,29.01 7.92,29.01 7.63,29.29 4.36,29.29 4.25,29.18 v1(3.89,29.18) ; v1(41.03,5.82) 40.37,5.82 39.85,5.3 34.89,5.3 34.02,6.17 24.44,6.17 23.73,5.46 23.73,3.05 21.44,0.76 12.32,0.76 8.56,4.52 5.91,4.52 4.59,3.2 1.5,3.2 0.59,4.11 0.59,29.51 v1(0.83,29.75)
  BOTTOM w0.058: MCU1.C12 13.9,27.26 14.15,27.51 14.15,27.94 13.39,28.7 11.99,28.7 11.66,29.03 v1(10.82,29.03)
  BOTTOM w0.066: v1(0.83,29.75) 1.07,29.51 1.73,29.51 1.91,29.34 3.45,29.34 3.61,29.18 v1(3.89,29.18)
MCU_LED2_RED_D: length 8.9
  TOP w0.066: v3(40.18,4.68) 40.18,4.73 40.43,4.98 46.48,4.98 47.45,4.01 D27402.2
  S3 w0.064: v3(40.18,4.68) 40.23,4.73 40.72,4.73 v4(40.82,4.63)
  S6 w0.064: v4(40.82,4.63) 40.82,4.67 41,4.85 v1(41.03,4.85)
MCU_MCO_PA8: length 57.5
  S6 w0.064: v5(4.39,24.61) 3.91,24.13 3.91,15.39 4.7,14.6 4.7,6.81 6.11,5.4 9.07,5.4 11.13,3.35 15.53,3.35 v1(15.62,3.26)
  G7 w0.064: v1(11.89,24.66) 11.68,24.66 11.48,24.87 8.76,24.87 8.23,24.33 7.7,24.33 7.44,24.08 6.45,24.08 5.92,24.61 v5(4.39,24.61)
  BOTTOM w0.066: v1(15.62,3.26) 16.08,3.72 23.3,3.72 23.55,3.97 23.55,4.97 24.8,6.22 30.16,6.22 31.11,7.17 JMISC1.23
MCU_NRST: length 92.3
  TOP w0.066: JSPI1.5 25.16,4.66 20.98,4.66 20.73,4.41 19.06,4.41 v3(18.73,4.74)
  S3 w0.064: v4(14,32.72) 7.26,32.72 v4(7.17,32.63) ; v4(14.51,34.86) 14.65,34.72 v4(19.46,34.72) ; v3(18.73,4.74) 18.73,5.03 18.07,5.69 14.11,5.69 12.58,7.22 8.21,7.22 7.79,6.8 5.7,6.8 4.63,5.73 3.76,5.73 3.22,6.27 1.39,6.27 0.91,6.75 0.91,18.37 2.5,19.96 v4(2.5,20.47)
  S6 w0.064: v4(14.51,34.86) 14.42,34.77 14.42,33.14 v4(14,32.72) ; v1(6.2,36.19) 7.17,35.22 v4(7.17,32.63) 7.17,30.84 4.95,28.62 4.95,22.99 v5(4.88,22.91) ; v1(19.28,37.9) 19.36,37.82 19.36,36.97 19.66,36.67 19.66,34.92 v4(19.46,34.72) ; v4(2.5,20.47) v5(3.48,20.47)
  G7 w0.064: v5(3.48,20.47) 3.48,20.97 4.88,22.37 v5(4.88,22.91) 4.95,22.99 8.28,22.99 8.46,23.16 10.06,23.16 10.21,23.32 10.49,23.32 10.9,22.91 11.05,22.91 11.35,22.61 v1(11.4,22.61)
  BOTTOM w0.066: v1(19.28,37.9) 19.28,38.27 18.64,38.91 17.46,38.91 U1101.7 ; TP2602.1 6.65,36.53 6.65,36.52 R2622.2 v1(6.2,36.19) 5.57,35.56 JANALOG1.3
MCU_NRST_1P8V: length 9.2
  S3 w0.064: v3(24.57,39.68) 24.15,39.68 23.86,39.39 19.72,39.39 v4(19.55,39.56)
  S6 w0.064: v4(19.55,39.56) v1(19.26,39.56)
  BOTTOM w0.066: U1101.5 16.05,39.18 16.5,39.63 19.19,39.63 v1(19.26,39.56)
MCU_OPAMP1_ VINM_PA1: length 52.5
  S6 w0.064: v5(5.38,21.56) 5.28,21.46 5.28,20.42 4.7,19.84 4.7,15.71 5.36,15.05 5.36,7.15 6.4,6.11 9.36,6.11 9.5,5.97 12.54,5.97 13.27,5.24 v5(13.46,5.24)
  G7 w0.064: v5(13.46,5.24) 13.57,5.35 18.35,5.35 19.18,6.18 19.18,8.12 19.54,8.48 19.54,10.59 v1(19.42,10.71) ; v5(5.38,21.56) 5.49,21.56 6.45,22.53 8.46,22.53 8.64,22.71 9.8,22.71 v1(9.9,22.61)
  BOTTOM w0.066: v1(19.42,10.71) 19.64,10.93 21.58,10.93 21.71,10.79 30.68,10.79 31.11,11.22 31.11,11.98
MCU_OPAMP1_ VINP_PA0: length 55
  S6 w0.064: v5(5.25,21.93) 5.13,21.82 5.13,20.47 4.55,19.89 4.55,15.65 5.23,14.97 5.23,7.1 6.35,5.98 9.31,5.98 9.5,5.79 12.46,5.79 13.21,5.04 v5(13.66,5.04)
  G7 w0.064: v5(13.66,5.04) 13.77,5.15 18.44,5.15 19.38,6.09 19.38,8.03 19.74,8.39 19.74,10.51 v1(19.9,10.67) ; v5(5.25,21.93) 5.64,21.93 6.39,22.68 8.39,22.68 8.57,22.86 10.15,22.86 v1(10.4,22.61)
  BOTTOM w0.066: v1(19.9,10.67) 19.95,10.72 21.52,10.72 21.62,10.62 32.12,10.62 32.38,10.88 32.38,11.98
MCU_OPAMP1_VOUT_PA3: length 52.4
  S6 w0.064: v1(6.04,7.21) 7.75,7.21 8.53,6.43 10.97,6.43 11.27,6.13 12.6,6.13 13.13,5.6 v5(13.38,5.6) ; v5(17.42,5.57) 16.95,6.04 16.95,9.44 v1(16.77,9.62)
  G7 w0.066: v5(17.42,5.57) 17.39,5.6 v5(13.38,5.6)
  BOTTOM w0.058: MCU1.N2 8.57,22.11 8.28,21.82 8.28,21.71 8.28,21.71 8.28,21.39 7.98,21.09 6.39,21.09 5.68,20.38
  BOTTOM w0.066: 5.68,20.38 5.68,10.3 6.04,9.94 v1(6.04,7.21) ; 33.65,11.98 33.65,10.79 33.3,10.44 18.56,10.44 18.21,10.09 17.24,10.09 v1(16.77,9.62)
MCU_OSC32_IN_PC14: length 1.7
  BOTTOM w0.066: R2514.2 14.07,20.3 13.4,20.97 MCU1.D1
MCU_OSC32_OUT_PC15: length 1.7
  BOTTOM w0.066: MCU1.E1 12.9,21.16 13.49,20.57 R2513.1
MCU_OSC_IN_PH0_R: length 1.6
  BOTTOM w0.066: R2509.1 10.59,20.81 MCU1.H1
MCU_OSC_OUT_PH1_R: length 1.6
  BOTTOM w0.066: MCU1.J1 10.9,21.39 10.06,20.55 R2511.1
MCU_PA4: length 8.9
  G7 w0.064: v1(6.1,20.17) v1(3.48,20.17)
  BOTTOM w0.058: v1(6.1,20.17) 6.74,20.81 8.15,20.81 8.9,21.56 MCU1.N1
  BOTTOM w0.066: v1(3.48,20.17) 3.63,20.02 3.63,18.87 JANALOG1.9
MCU_PA5: length 13.7
  G7 w0.064: v1(4.03,20.92) 4.03,21.2 5.66,22.83 8.33,22.83 8.51,23.01 10.3,23.01 v1(10.4,23.11)
  BOTTOM w0.066: JANALOG1.10 2.54,16.08 3.84,17.37 3.84,20.73 v1(4.03,20.92)
MCU_PA6: length 23.9
  BOTTOM w0.058: 4.95,21.08 4.95,12.85 3.78,11.68 3.78,9.58 3.02,8.81 1.84,8.81 0.97,9.68 0.97,10.9 2.54,12.47 JANALOG1.11 ; MCU1.N4 8.58,23.11 7.84,22.37 6.24,22.37
  BOTTOM w0.066: 6.24,22.37 4.95,21.08
MCU_PA7: length 19
  BOTTOM w0.058: JANALOG1.12 2.54,10.64 4.81,12.91 4.81,21.17 ; MCU1.J5 10.63,23.34 8.61,23.34 7.79,22.52 6.16,22.52
  BOTTOM w0.066: 6.16,22.52 4.81,21.17
MCU_PA11: length 82.9
  S3 w0.064: JDIGITAL1.6 49,15.98 49,7.15 47.64,5.79 32.93,5.79 31.64,7.09 24.09,7.09 23.13,6.13 23.13,4.07 20.87,1.81 18.39,1.81 v4(17.83,2.36)
  S6 w0.064: v4(17.83,2.36) 17.83,2.49 11.5,8.82 8.91,8.82 6.92,10.81 6.92,12.81 7.09,12.98 7.09,17.31 9.14,19.37 9.14,21.36 8.61,21.9 8.61,23.24 9.45,24.08 9.45,24.14 9.46,24.15 9.46,27.62 v5(9.91,28.07)
  G7 w0.064: v1(11.9,27.61) 11.37,28.14 9.98,28.14 v5(9.91,28.07)
MCU_PA12: length 81.7
  S3 w0.064: v4(16.97,2.64) 17.07,2.64 18.08,1.63 20.94,1.63 23.31,4 23.31,6.05 24.17,6.91 31.56,6.91 32.86,5.61 47.81,5.61 49.17,6.97 49.17,13.61 JDIGITAL1.5
  S6 w0.064: v4(16.97,2.64) 16.97,2.93 11.38,8.52 8.86,8.52 6.62,10.76 6.62,12.93 6.79,13.1 6.79,17.43 8.31,18.96 8.31,19.74 8.47,19.9 8.47,23.3 8.48,23.31 8.48,23.37 9.32,24.21 9.32,27.94 v5(9.42,28.04)
  G7 w0.064: v1(12.4,27.61) 11.72,28.3 9.68,28.3 v5(9.42,28.04)
MCU_PB0: length 73.8
  S3 w0.064: JDIGITAL1.4 49.35,11.25 49.35,6.9 47.89,5.44 32.78,5.44 31.49,6.73 24.24,6.73 23.49,5.98 23.49,3.92 21.02,1.45 18.01,1.45 17.25,2.21 v4(16.69,2.21)
  S6 w0.064: v5(8.23,23.27) 8.33,23.16 8.33,19.97 8.16,19.8 8.16,19.02 6.64,17.5 6.64,13.17 6.47,13 6.47,10.74 8.84,8.37 11.32,8.37 16.61,3.07 16.61,2.29 v4(16.69,2.21)
  G7 w0.064: v1(10.4,23.61) 10.2,23.61 9.98,23.39 8.36,23.39 v5(8.23,23.27)
MCU_PB1: length 81.4
  S3 w0.064: JDIGITAL1.7 48.82,18.34 48.82,7.27 47.52,5.97 33.01,5.97 31.71,7.26 24.02,7.26 22.96,6.2 22.96,4.14 20.8,1.98 18.73,1.98 18.02,2.69 17.42,2.69 17.11,3 16.18,3 v4(15.98,2.79)
  S6 w0.064: v4(15.98,2.79) 15.98,3.3 11.2,8.08 8.78,8.08 6.15,10.71 6.15,15.19 5.33,16 5.33,19.63 6.2,20.5 6.2,22.28 5.94,22.53 5.84,22.53 v1(5.82,22.56)
  BOTTOM w0.058: 5.93,22.67 7.74,22.67 8.68,23.61
  BOTTOM w0.066: 8.68,23.61 MCU1.N5 ; v1(5.82,22.56) 5.93,22.67
MCU_PB2: length 80.7
  S3 w0.064: v4(17.83,3) 18.18,3 19.05,2.13 20.69,2.13 22.78,4.22 22.78,6.28 23.94,7.44 31.78,7.44 33.08,6.15 47.4,6.15 48.64,7.39 48.64,20.7 JDIGITAL1.8
  S6 w0.064: v4(17.83,3) 17.55,3 11.58,8.97 8.93,8.97 7.07,10.83 7.07,12.75 7.24,12.92 7.24,17.25 9.3,19.3 9.3,21.54 8.76,22.07 8.76,23.06 8.99,23.29 9.58,23.29 v1(9.9,23.61)
MCU_PB8: length 77.5
  TOP w0.066: JDIGITAL1.10 49.34,28 49.34,6.97 48.69,6.32 24.59,6.32 23.24,4.97 18.19,4.97 v3(18.12,4.9)
  S3 w0.064: v3(18.12,4.9) 18.01,5.01 v4(17.81,5.01)
  S6 w0.064: v4(17.81,5.01) 17.81,5.57 17.11,6.27 17.11,9.72 11.56,15.27 11.56,16.92 v5(12.45,17.81)
  G7 w0.064: v5(12.45,17.81) 12.41,17.84 12.41,19.32 12.65,19.56 v1(12.65,19.76)
  BOTTOM w0.051: 12.65,21.21 12.65,23.36 MCU1.E5
  BOTTOM w0.066: v1(12.65,19.76) 12.75,19.86 12.75,20.65 12.57,20.83 12.57,21.13 12.65,21.21
MCU_PC0: length 23.1
  G7 w0.064: v1(5.84,21.23) 6.25,21.65 10.72,21.65 10.9,21.82 v1(10.9,22.11)
  BOTTOM w0.058: JANALOG1.14 3.76,6.3 3.76,9.04 4.11,9.4 4.11,11.4 5.31,12.6 5.31,20.7 v1(5.84,21.23)
MCU_PC1: length 21.3
  G7 w0.064: v1(5.44,21.21) 6.36,22.13 8.04,22.13 8.35,21.82 10.46,21.82 10.61,21.97 10.61,22.33 v1(10.9,22.61)
  BOTTOM w0.058: v1(5.44,21.21) 5.16,20.93 5.16,12.75 3.96,11.56 3.96,9.5 2.54,8.08 JANALOG1.13
MCU_PE7: length 65
  G7 w0.064: v1(4.12,22.95) 4.12,22.74 3,21.62 3,19.19 4.04,18.15 4.04,13.72 3.74,13.42 3.74,6.05 3.99,5.8 17.81,5.8 18.29,6.28 18.29,6.93 18.76,7.4 18.76,9.76 v1(18.82,9.82)
  BOTTOM w0.058: MCU1.L7 9.65,24.86 8.76,24.86 ; 7.69,23.79 7.11,23.79 6.49,23.17
  BOTTOM w0.066: v1(4.12,22.95) 4.43,22.64 4.98,22.64 5.51,23.17 6.49,23.17 ; v1(18.82,9.82) 19.14,10.14 38.1,10.14 38.73,10.77 38.73,11.98 ; 7.69,23.79 8.76,24.86
MCU_PE8: length 64.2
  G7 w0.064: v1(4.46,22.95) 4.46,22.9 3.13,21.57 3.13,19.24 4.17,18.2 4.17,13.67 3.87,13.37 3.87,6.15 4.08,5.94 17.75,5.94 18.15,6.34 18.15,6.99 18.62,7.46 18.62,10.1 v1(18.65,10.13)
  BOTTOM w0.058: 5.17,23.12 5.37,23.32 6.44,23.32 7.05,23.93 7.54,23.93 8.62,25.01 8.62,25.29 8.68,25.35 10,25.35 10.14,25.21 10.14,24.96 10.4,24.7 MCU1.K7
  BOTTOM w0.066: 37.46,11.98 37.46,11.04 36.71,10.29 18.81,10.29 v1(18.65,10.13) ; 5.17,23.12 4.63,23.12 v1(4.46,22.95)
MCU_PSSI_D0: length 49.5
  S6 w0.064: v1(13.16,27.38) 12.9,27.13 12.9,26.44 13.16,26.19 13.16,21.67 13.82,21.01 13.82,17.42 16.02,15.22 16.02,13.67 23.04,6.65 43.57,6.65 45,8.08 v1(45.08,8.08)
  BOTTOM w0.051: v1(13.16,27.38) 11.63,27.38 MCU1.H13
MCU_PSSI_D1: length 46.7
  S6 w0.064: v1(43.81,8.08) 43.73,8.08 42.48,6.83 23.09,6.83 16.15,13.77 16.15,15.32 13.97,17.5 13.97,21.08 13.31,21.74 13.31,26.7 v1(13.15,26.86)
  BOTTOM w0.051: MCU1.G12 12.15,26.86 v1(13.15,26.86)
MCU_PSSI_D2: length 44.6
  S6 w0.064: v1(42.54,8.08) 42.46,8.08 41.41,7.04 23.07,7.04 16.28,13.83 16.28,15.44 14.15,17.58 14.15,21.15 13.49,21.81 13.49,25.78 v5(13.61,25.91)
  G7 w0.064: v1(11.9,26.11) 12.1,25.91 v5(13.61,25.91)
MCU_PSSI_D3: length 42.9
  S6 w0.064: v5(13.85,25.53) 13.87,25.53 13.64,25.3 13.64,21.95 14.35,21.23 14.35,17.58 16.42,15.51 16.42,13.9 23.11,7.21 40.31,7.21 41.19,8.08 v1(41.27,8.08)
  G7 w0.064: v1(11.9,25.61) 13.78,25.61 13.87,25.53 13.87,25.53 v5(13.85,25.53)
MCU_PSSI_D4: length 35.7
  S6 w0.064: v1(40,8.08) 39.92,8.08 39.18,7.34 23.19,7.34 16.54,13.99 16.54,15.62 14.53,17.63 14.53,21.44 13.9,22.07 13.9,22.1 v1(13.89,22.1)
MCU_PSSI_D5: length 38.9
  S6 w0.05: 38.36,7.62 38.22,7.48 34.36,7.48
  S6 w0.064: 38.36,7.62 38.65,7.91 v1(38.73,7.91) ; 34.36,7.48 23.25,7.48 16.68,14.06 16.68,15.71 14.73,17.65 14.73,21.56 14.13,22.16 14.13,22.19 13.98,22.35 13.95,22.35 13.89,22.4 13.89,25.24 14.08,25.43 14.08,25.62 14.08,25.85 14.08,25.85 14.08,25.97 14.13,26.02 14.13,26.21 14.12,26.22 14.12,26.29 v1(14.17,26.34)
  BOTTOM w0.051: v1(14.17,26.34) 14.17,26.32 MCU1.B10
MCU_PSSI_D6: length 32.2
  S6 w0.064: v1(14.9,22.11) 14.94,22.08 14.94,17.68 16.83,15.78 16.83,14.1 23.31,7.62 37.18,7.62 v1(37.46,7.91)
MCU_PSSI_D7: length 32.5
  S6 w0.064: v5(14.22,22.43) 14.23,22.43 14.9,22.43 15.13,22.2 15.13,17.74 16.97,15.9 16.97,14.15 23.36,7.76 35.83,7.76 v5(36.2,8.13)
  G7 w0.064: v5(36.2,8.13) 36.19,8.13 v1(36.19,7.91) ; v5(14.22,22.43) 14.16,22.49 14.02,22.49 v1(13.9,22.61)
MCU_PSSI_DE: length 72.9
  S6 w0.064: v1(15.63,2.91) 14.98,2.91 14.89,3 11.02,3 8.99,5.03 5.71,5.03 4.53,3.85 1.97,3.85 1.1,4.71 1.1,26.38 1.32,26.59 v5(1.7,26.59)
  G7 w0.064: v5(1.7,26.59) 3.89,26.59 5.13,27.84 8.81,27.84 9.25,27.41 9.75,27.41 v1(9.91,27.25)
  BOTTOM w0.066: v1(15.63,2.91) 16.26,3.54 23.55,3.54 24.1,2.99 24.1,1.44 24.37,1.17 31.35,1.17 32.21,2.03 32.21,7.91 JMISC1.21 ; v1(9.91,27.25) 9.9,27.25 MCU1.L12
MCU_PSSI_PDCK: length 75.1
  S6 w0.064: v5(1.68,26.95) 1.42,26.95 0.93,26.45 0.93,4.64 1.89,3.67 4.6,3.67 5.68,4.75 9,4.75 10.9,2.85 14.82,2.85 15.13,2.54 v1(15.61,2.54)
  G7 w0.064: v5(1.68,26.95) 1.78,26.95 1.98,26.75 3.82,26.75 5.07,27.99 8.86,27.99 9.24,27.61 v1(9.9,27.61)
  BOTTOM w0.066: JMISC1.17 34.92,7.47 34.16,6.71 34.16,5.66 32.64,4.14 32.64,1.85 31.57,0.79 24.49,0.79 23.87,1.41 23.87,2.93 23.44,3.36 16.43,3.36 v1(15.61,2.54)
MCU_PSSI_RDY: length 35.7
  S6 w0.064: v5(12.88,22.78) 12.93,22.73 12.93,22.28 12.88,22.23 12.88,17.71 13.99,16.6 14.36,16.6 15.81,15.15 15.81,13.69 23.01,6.49 32.91,6.49 v1(33.65,5.75)
  G7 w0.064: v5(12.88,22.78) 12.95,22.86 14.15,22.86 v1(14.2,22.81)
  BOTTOM w0.066: MCU1.B3 v1(14.2,22.81) ; JMISC1.19 v1(33.65,5.75)
MCU_SDMMC1_CMD_PD2: length 73
  S6 w0.064: v5(4.47,24.28) 4.34,24.28 4.06,24 4.06,15.45 4.83,14.68 4.83,6.9 6.17,5.56 9.13,5.56 9.39,5.3 12.29,5.3 13.21,4.38 14.25,4.38 v5(14.3,4.43)
  G7 w0.064: v5(14.3,4.43) 14.44,4.57 18.87,4.57 20.31,6.01 20.31,8.95 v1(20.45,9.09) ; v5(4.47,24.28) 6.02,24.28 6.38,23.93 7.5,23.93 7.76,24.18 9.4,24.18 9.65,24.43 12.22,24.43 v1(12.4,24.61)
  BOTTOM w0.066: v1(20.45,9.09) 20.51,9.15 41.74,9.15 43.34,10.75 44.76,10.75 45.08,11.07 JMISC1.2
MCU_SOC_LPUART1_CTS: length 4.8
  G7 w0.064: v1(10.9,25.61) 8.89,25.61 7.88,24.6 6.85,24.6 v1(6.62,24.83)
MCU_SOC_LPUART1_RTS: length 4.9
  G7 w0.064: v1(6.96,27.05) 6.96,27 7.47,26.48 8.61,26.48 8.98,26.11 v1(11.4,26.11)
MCU_SOC_LPUART1_RX: length 4.6
  G7 w0.064: v1(11.4,25.61) 11.15,25.86 7.11,25.86 v1(6.96,26.01)
MCU_SOC_LPUART1_TX: length 5.2
  G7 w0.064: v1(7.14,24.36) 7.24,24.46 8.03,24.46 8.89,25.32 11.69,25.32 v1(11.9,25.11)
MCU_SPI2_CLK: length 1.6
  BOTTOM w0.051: 8.46,28.05 MCU1.N13
  BOTTOM w0.066: R2641.1 8.46,28.05
MCU_SPI2_CLK_CONN: length 104.2
  TOP w0.058: JDIGITAL1.14 48.74,37.56 48.74,7.21 48.54,7.01 24.23,7.01 ; 11.99,4.28 v3(11.99,5.84)
  TOP w0.066: 24.23,7.01 22.85,5.64 17.77,5.64 15.82,3.68 12.59,3.68 11.99,4.28
  S3 w0.064: v4(12.27,6.43) 12.11,6.43 11.99,6.31 v3(11.99,5.84)
  S6 w0.064: v1(5.82,28.32) 5.8,28.32 5.74,28.26 5.74,23.95 5.54,23.75 5.54,22.48 6.02,22 6.02,20.52 5.18,19.68 5.18,15.9 5.99,15.09 5.99,10.69 8.75,7.93 10.74,7.93 12.24,6.43 v4(12.27,6.43)
  BOTTOM w0.066: R2641.2 8.34,29.61 7.41,29.61 6.99,29.19 6.31,29.19 5.82,28.7 v1(5.82,28.32)
MCU_SPI2_CLK_PD1: length 54.3
  TOP w0.066: v3(18.4,4.72) 18.9,4.22 R2617.1
  S3 w0.064: v4(1.96,24.05) 0.71,22.81 0.71,10.05 0.71,10.04 0.71,4.78 1.77,3.72 4.32,3.72 5.77,5.17 6.45,5.17 8.35,7.07 12.45,7.07 14.11,5.41 18.03,5.41 18.4,5.04 v3(18.4,4.72)
  S6 w0.064: v5(2.26,24.1) 2.21,24.05 v4(1.96,24.05)
  G7 w0.064: v1(12.4,24.11) 12.2,24.31 9.7,24.31 9.44,24.04 7.82,24.04 7.56,23.79 4.58,23.79 4.27,24.1 v5(2.26,24.1)
MCU_SPI2_CLK_PD1_CONN: length 7
  TOP w0.058: 26.75,3.71 JSPI1.3
  TOP w0.066: R2617.2 22.28,4.22 22.79,3.71 26.75,3.71
MCU_SPI2_MISO: length 2
  BOTTOM w0.051: 9.14,28.83 9.14,27.37 MCU1.M12
  BOTTOM w0.066: 9.14,28.83 R2640.1
MCU_SPI2_MISO_CONN: length 102.7
  TOP w0.058: 11.71,4.31 v3(11.71,5.49) ; JDIGITAL1.13 48.88,35.16 48.88,7.15 48.56,6.83 24.3,6.83
  TOP w0.066: 24.3,6.83 22.93,5.46 17.85,5.46 15.9,3.51 12.51,3.51 11.71,4.31
  S3 w0.064: v4(11.48,6.45) 11.48,5.94 11.71,5.71 v3(11.71,5.49)
  S6 w0.064: v4(11.48,6.45) 11.48,6.64 10.35,7.78 8.72,7.78 5.83,10.67 5.83,15.03 5.02,15.83 5.02,19.73 5.87,20.57 5.87,21.92 5.38,22.4 5.38,23.81 5.59,24.02 5.59,28.17 v1(5.46,28.3)
  BOTTOM w0.066: v1(5.46,28.3) 5.49,28.32 5.49,28.85 6.03,29.4 6.94,29.4 7.35,29.8 8.68,29.8 R2640.2
MCU_SPI2_MISO_PC2: length 37.9
  TOP w0.058: v3(10.02,5.42) 10.02,5.19 12.24,2.97 17.59,2.97
  TOP w0.066: 17.59,2.97 20.51,2.97 R2618.1
  S3 w0.064: v3(10.02,5.42) 10.01,5.42 v4(8.68,6.75)
  S6 w0.064: v1(5.7,7.46) 7.83,7.46 8.54,6.75 v4(8.68,6.75)
  BOTTOM w0.058: 6.3,22.23 7.9,22.23 8.53,22.86
  BOTTOM w0.066: v1(5.7,7.46) 5.73,7.49 5.73,9.94 5.51,10.16 5.51,20.42 6.1,21.01 6.1,22.02 6.3,22.23 ; 8.53,22.86 10.65,22.86 MCU1.J4
MCU_SPI2_MISO_PC2_CONN: length 9.4
  TOP w0.058: 22.72,3.57 29.15,3.57 JSPI1.1
  TOP w0.066: R2618.2 21.7,3.57 22.72,3.57
MCU_SPI2_MOSI: length 4.3
  G7 w0.064: v1(7.37,28.75) 7.62,28.5 v1(9.55,28.5)
  BOTTOM w0.066: MCU1.L11 9.65,26.86 9.65,28.4 v1(9.55,28.5)
MCU_SPI2_MOSI_CONN: length 97.8
  TOP w0.058: v3(11.2,5.49) 11.2,4.52 12.37,3.35 ; 24.36,6.68 48.62,6.68 49.03,7.1 49.03,32.77 JDIGITAL1.12
  TOP w0.066: 24.36,6.68 22.99,5.31 17.91,5.31 15.96,3.35 12.37,3.35
  S3 w0.064: v4(10.85,6.72) 11.02,6.55 11.02,5.66 v3(11.2,5.49)
  S6 w0.064: v1(6.12,28.63) 6.1,28.65 5.31,28.65 5.21,28.55 5.21,22.33 5.71,21.82 5.71,20.62 4.86,19.76 4.86,15.77 5.66,14.96 5.66,10.65 8.69,7.62 9.83,7.62 10.73,6.72 v4(10.85,6.72)
  BOTTOM w0.066: R2626.2 6.2,28.75 6.12,28.68 v1(6.12,28.63)
MCU_SPI2_MOSI_PC3: length 34.6
  TOP w0.058: v3(9.88,5.82) 9.78,5.71 9.78,5.13 12.14,2.77 17.68,2.77
  TOP w0.066: 17.68,2.77 20.91,2.77 R2619.1
  S3 w0.064: v3(9.88,5.82) 9.88,6.27 v4(9.46,6.69)
  S6 w0.064: v4(9.46,6.69) 8.84,7.31 8.55,7.31 6.96,8.9 6.79,8.9 6.46,9.23 v1(6.46,9.47)
  BOTTOM w0.058: MCU1.K1 10.17,21.84 9.26,21.84 9.15,21.73 ; 8.21,20.67 8.59,21.05 8.83,21.05 9.15,21.37
  BOTTOM w0.066: 8.21,20.67 7.03,20.67 6.48,20.12 6.48,19.57 6.04,19.13 6.04,17.76 5.84,17.56 5.84,10.45 6.46,9.83 v1(6.46,9.47) ; 9.15,21.37 9.15,21.73
MCU_SPI2_MOSI_PC3_CONN: length 7.6
  TOP w0.066: JSPI1.4 27.95,2.35 26.7,1.09 23.95,1.09 22.07,2.98 R2619.2
MCU_SPI2_NSS: length 9.4
  G7 w0.064: v1(7.8,19.76) 8.03,19.76 8.36,20.09 13,20.09 v1(13.87,20.95)
  BOTTOM w0.051: MCU1.D5 13.64,23.37
  BOTTOM w0.066: v1(13.87,20.95) 13.64,21.18 13.64,23.37
MCU_SPI2_NSS_CONN: length 84
  TOP w0.058: 10.72,4.8 v3(10.72,5.41) ; 24.43,6.51 48.65,6.51 49.18,7.04 49.18,30.38 JDIGITAL1.11
  TOP w0.066: 10.72,4.8 12.38,3.14 15.98,3.14 17.98,5.14 23.06,5.14 24.43,6.51
  S3 w0.064: v3(10.72,5.41) 10.44,5.69 10.44,6.43 v4(10.16,6.71)
  S6 w0.064: v1(6.73,9.28) 6.83,9.28 8.67,7.44 9.42,7.44 v4(10.16,6.71)
  BOTTOM w0.066: R2625.2 6.05,17.5 6.05,10.49 6.73,9.81 v1(6.73,9.28)
MCU_SPI3_CLK: length 13.6
  S3 w0.05: v3(27.37,28.88) 27.37,28.68
  S3 w0.064: 27.37,28.68 25.99,27.3 22.53,27.3 22,26.77 19.13,26.77 v4(19.02,26.67)
  S6 w0.064: v1(18.72,26.64) 19,26.64 v4(19.02,26.67)
  BOTTOM w0.066: R2505.2 17.09,24.66 17.17,24.59 18.34,24.59 18.72,24.97 v1(18.72,26.64)
MCU_SPI3_CLK_R: length 1.3
  BOTTOM w0.051: 16.13,24.66 14.95,24.66 MCU1.A7
MCU_SPI3_CS_N: length 37.6
  TOP w0.066: SOC1.AA30 27.37,25.67 26.45,24.75 26.45,23.64 25.33,22.52 25.33,17.95 v3(25.55,17.73)
  S3 w0.066: v3(25.55,17.73) 25.45,17.63 21.49,17.63 19.67,15.81 18.71,15.81 18.34,15.44 11.98,15.44 11.29,16.13 6.3,16.13 v4(6.05,15.88)
  S6 w0.064: v4(6.05,15.88) 6.27,16.1 v1(6.27,19.03)
  BOTTOM w0.066: v1(6.27,19.03) 6.68,19.44 6.68,19.95 7.04,20.31 R2508.2
MCU_SPI3_CS_N_R: length 15.2
  S6 w0.064: v5(4.34,23.65) 4.32,23.62 v5(4.32,21.18)
  G7 w0.064: v5(4.32,21.18) 4.52,20.98 5.11,20.98 5.31,20.78 7.34,20.78 v1(7.75,20.37) ; v5(4.34,23.65) 7.62,23.65 7.87,23.9 9.49,23.9 9.78,24.19 10.93,24.19 11.23,23.9 12.69,23.9 v1(12.9,24.11)
MCU_SPI3_MISO: length 40.7
  TOP w0.05: 28.17,28.33 28.17,28.48
  TOP w0.066: v3(25.56,18.03) 25.61,18.08 25.61,22.42 28.17,24.97 28.17,28.33
  S3 w0.064: v4(14.25,27.05) v4(18.69,27.05)
  S3 w0.066: v4(17.91,16.05) 18.39,16.05 18.95,16.61 20.19,16.61 21.36,17.78 25.12,17.78 25.37,18.03 v3(25.56,18.03)
  S6 w0.064: v4(17.91,16.05) 17.04,16.05 15.29,17.81 15.29,22.33 14.58,23.04 14.58,24.92 14.22,25.28 14.22,25.68 14.22,25.68 14.22,25.91 14.43,26.12 14.43,26.87 v4(14.25,27.05) ; v4(18.69,27.05) 18.62,27.13 v1(18.62,27.36)
  BOTTOM w0.066: R2506.2 18.39,25.27 18.39,27.13 v1(18.62,27.36)
MCU_SPI3_MISO_R: length 3.8
  BOTTOM w0.051: 15.65,24.84 14.13,24.84 MCU1.C7
  BOTTOM w0.066: R2506.1 16.92,24.92 16.81,25.02 15.82,25.02 15.65,24.84
MCU_SPI3_MOSI_1P8V: length 26.1
  S3 w0.064: v4(14.53,25.73) 14.96,26.16 21.89,26.16 22.73,27 26.17,27 27.77,28.6 v3(27.77,28.91)
  S6 w0.064: v4(14.53,25.73) 14.63,25.83 14.63,29.35 14.41,29.57 v1(14.41,32.48)
  BOTTOM w0.066: U1102.3 18.04,33.51 17.58,33.05 14.98,33.05 v1(14.41,32.48)
MCU_SPI3_MOSI_3P3V: length 13.3
  G7 w0.064: v1(19.17,22.56) 19.57,22.56 19.86,22.85 19.86,28.6 19.68,28.78 19.68,30.64 v1(19.64,30.69)
  BOTTOM w0.066: v1(19.17,22.56) 19.11,22.56 18.76,22.91 R2507.1 ; U1102.4 18.04,31.18 18.53,30.69 v1(19.64,30.69)
MCU_SPI3_MOSI_R: length 2.9
  BOTTOM w0.051: MCU1.C6 14.13,23.88 15.37,23.88
  BOTTOM w0.066: 15.37,23.88 R2507.2
MCU_SPI3_RDY: length 44
  S3 w0.05: 27.94,28.33 28.17,28.56 v3(28.17,28.88)
  S3 w0.064: 27.94,28.33 26.31,26.7 22.83,26.7 21.96,25.83 17.92,25.83 15.92,23.83 15.92,17.51 15.32,16.91 6.68,16.91 6.43,17.17 6.02,17.17 v4(5.84,17.35)
  S6 w0.064: v4(5.84,17.35) 5.84,19.25 v5(5.77,19.33)
  G7 w0.064: v5(5.77,19.33) v1(4.22,19.33)
  BOTTOM w0.058: 4.27,21.87 4.27,19.38 v1(4.22,19.33)
  BOTTOM w0.066: R2516.2 6.15,26.83 5.57,26.24 5.57,25.54 3.81,23.78 3.81,22.33 4.27,21.87
MCU_SPI3_RDY_R: length 3.1
  BOTTOM w0.066: MCU1.N10 8.47,25.68 6.66,25.68 6.52,25.82 R2516.1
